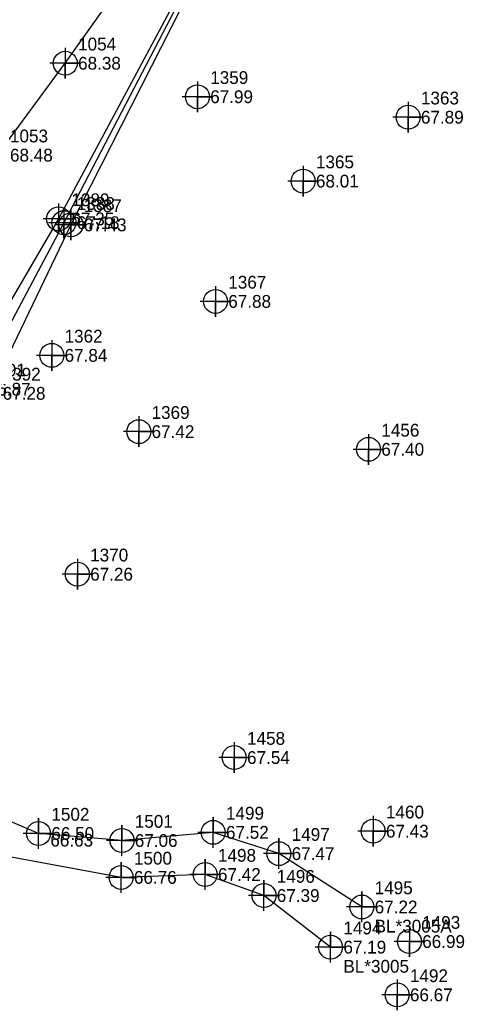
# Model space of a CAD drawing. Extents: x 2062781 to 2066835, y 358981 to 366501.
# Drawn here: x 2066461.7 to 2066548.6, y 365960.1 to 366153.9 of the extents above; entities that cross this region are included whole.
import ezdxf

# ---------------------------------------------------------------- set-up
doc = ezdxf.new("R2010")
doc.units = 0
for name, color, linetype in [('Exist DTM Breakline', 7, 'Continuous'), ('Exist DTM Breakline Cogo Elevation', 7, 'Continuous'), ('Exist DTM Breakline Cogo Number', 7, 'Continuous'), ('Exist DTM Breakline Cogo Point CELL', 7, 'Continuous'), ('Exist DTM Regular Point CELL', 7, 'Continuous'), ('Exist DTM Regular Point Cogo Elevation', 7, 'Continuous'), ('Exist DTM Regular Point Cogo Number', 7, 'Continuous'), ('Exist DTM Ridgeline', 7, 'Continuous'), ('Exist DTM Ridgeline Cogo Elevation', 7, 'Continuous'), ('Exist DTM Ridgeline Cogo Number', 7, 'Continuous'), ('Exist DTM Ridgeline Cogo Point CELL', 7, 'Continuous'), ('Exist Roads EOP', 7, 'Continuous'), ('Exist Roads EOP Cogo Elevation', 7, 'Continuous'), ('Exist Roads EOP Cogo Number', 7, 'Continuous'), ('Exist Roads EOP Cogo Point CELL', 7, 'Continuous'), ('Exist Roads Soil', 7, 'Continuous'), ('Exist Roads Soil Cogo Comment', 7, 'Continuous'), ('Exist Roads Soil Cogo Elevation', 7, 'Continuous'), ('Exist Roads Soil Cogo Number', 7, 'Continuous'), ('Exist Roads Soil Cogo Point CELL', 7, 'Continuous')]:
    doc.layers.add(name, color=color, linetype=linetype)

msp = doc.modelspace()

# ---------------------------------------------------------------- linework, layer by layer
at = {"layer": 'Exist DTM Breakline'}
msp.add_lwpolyline([(2066502.59, 366180.16), (2066494.49, 366160.63), (2066470.36, 366114.18), (2066452.98, 366081.59), (2066430.77, 366031.3)], dxfattribs=at)
at = {"layer": 'Exist DTM Breakline Cogo Point CELL'}
msp.add_lwpolyline([(2066470.36, 366117.18), (2066470.36, 366111.18), (2066470.36, 366114.18), (2066473.36, 366114.18), (2066467.36, 366114.18)], dxfattribs=at)
msp.add_circle((2066470.36, 366114.18), 2.34, dxfattribs=at)
at = {"layer": 'Exist DTM Regular Point CELL'}
for points in [[(2066496.44, 366141.83), (2066496.44, 366135.83), (2066496.44, 366138.83), (2066499.44, 366138.83), (2066493.44, 366138.83)], [(2066537.62, 366137.82), (2066537.62, 366131.82), (2066537.62, 366134.82), (2066540.62, 366134.82), (2066534.62, 366134.82)], [(2066517.1, 366125.32), (2066517.1, 366119.32), (2066517.1, 366122.32), (2066520.1, 366122.32), (2066514.1, 366122.32)], [(2066499.97, 366101.78), (2066499.97, 366095.78), (2066499.97, 366098.78), (2066502.97, 366098.78), (2066496.97, 366098.78)], [(2066467.98, 366091.22), (2066467.98, 366085.22), (2066467.98, 366088.22), (2066470.98, 366088.22), (2066464.98, 366088.22)], [(2066484.98, 366076.29), (2066484.98, 366070.29), (2066484.98, 366073.29), (2066487.98, 366073.29), (2066481.98, 366073.29)], [(2066529.88, 366072.83), (2066529.88, 366066.83), (2066529.88, 366069.83), (2066532.88, 366069.83), (2066526.88, 366069.83)], [(2066472.98, 366048.4), (2066472.98, 366042.4), (2066472.98, 366045.4), (2066475.98, 366045.4), (2066469.98, 366045.4)], [(2066503.64, 366012.52), (2066503.64, 366006.52), (2066503.64, 366009.52), (2066506.64, 366009.52), (2066500.64, 366009.52)], [(2066530.78, 365998.11), (2066530.78, 365992.11), (2066530.78, 365995.11), (2066533.78, 365995.11), (2066527.78, 365995.11)], [(2066537.87, 365976.51), (2066537.87, 365970.51), (2066537.87, 365973.51), (2066540.87, 365973.51), (2066534.87, 365973.51)], [(2066535.47, 365966.08), (2066535.47, 365960.08), (2066535.47, 365963.08), (2066538.47, 365963.08), (2066532.47, 365963.08)]]:
    msp.add_lwpolyline(points, dxfattribs=at)
for centre in [(2066496.44, 366138.83), (2066537.62, 366134.82), (2066517.1, 366122.32), (2066499.97, 366098.78), (2066467.98, 366088.22), (2066484.98, 366073.29), (2066529.88, 366069.83), (2066472.98, 366045.4), (2066503.64, 366009.52), (2066530.78, 365995.11), (2066537.87, 365973.51), (2066535.47, 365963.08)]:
    msp.add_circle(centre, 2.34, dxfattribs=at)
at = {"layer": 'Exist DTM Ridgeline'}
for points in [[(2066501.78, 366180.58), (2066493.93, 366161.06), (2066469.32, 366114.92), (2066450.36, 366082.49), (2066428.47, 366032.58)], [(2066503.5, 366179.71), (2066495.31, 366160.25), (2066471.73, 366113.76), (2066455.88, 366080.79), (2066433.24, 366030.24)]]:
    msp.add_lwpolyline(points, dxfattribs=at)
at = {"layer": 'Exist DTM Ridgeline Cogo Point CELL'}
for points in [[(2066469.32, 366117.92), (2066469.32, 366111.92), (2066469.32, 366114.92), (2066472.32, 366114.92), (2066466.32, 366114.92)], [(2066471.73, 366116.76), (2066471.73, 366110.76), (2066471.73, 366113.76), (2066474.73, 366113.76), (2066468.73, 366113.76)]]:
    msp.add_lwpolyline(points, dxfattribs=at)
for centre in [(2066469.32, 366114.92), (2066471.73, 366113.76)]:
    msp.add_circle(centre, 2.34, dxfattribs=at)
at = {"layer": 'Exist Roads EOP'}
msp.add_lwpolyline([(2066402.7, 366021.61), (2066413.52, 366042.85), (2066436.44, 366087.8), (2066457.31, 366127.4), (2066470.62, 366145.38), (2066484.82, 366165.44), (2066489.78, 366172.83), (2066491.22, 366174.84), (2066494.73, 366177.66), (2066498.24, 366180.15)], dxfattribs=at)
at = {"layer": 'Exist Roads EOP Cogo Point CELL'}
msp.add_lwpolyline([(2066470.62, 366148.38), (2066470.62, 366142.38), (2066470.62, 366145.38), (2066473.62, 366145.38), (2066467.62, 366145.38)], dxfattribs=at)
msp.add_circle((2066470.62, 366145.38), 2.34, dxfattribs=at)
at = {"layer": 'Exist Roads Soil'}
for points in [[(2066528.58, 365980.28), (2066512.36, 365990.72), (2066499.52, 365994.88), (2066481.7, 365993.28), (2066465.4, 365994.66), (2066450.12, 366001.21), (2066430.48, 366010.74), (2066407.05, 366015.41)], [(2066481.53, 365986.07), (2066446.25, 365992.58), (2066424.19, 366000.79), (2066400, 366001.24)], [(2066522.47, 365972.42), (2066509.45, 365982.52), (2066497.96, 365986.63), (2066481.53, 365986.07)]]:
    msp.add_lwpolyline(points, dxfattribs=at)
at = {"layer": 'Exist Roads Soil Cogo Point CELL'}
for points in [[(2066465.4, 365991.66), (2066465.4, 365997.66), (2066465.4, 365994.66), (2066468.4, 365994.66), (2066462.4, 365994.66)], [(2066481.7, 365990.28), (2066481.7, 365996.28), (2066481.7, 365993.28), (2066484.7, 365993.28), (2066478.7, 365993.28)], [(2066499.52, 365991.88), (2066499.52, 365997.88), (2066499.52, 365994.88), (2066502.52, 365994.88), (2066496.52, 365994.88)], [(2066512.36, 365987.72), (2066512.36, 365993.72), (2066512.36, 365990.72), (2066515.36, 365990.72), (2066509.36, 365990.72)], [(2066481.53, 365983.07), (2066481.53, 365989.07), (2066481.53, 365986.07), (2066484.53, 365986.07), (2066478.53, 365986.07)], [(2066497.96, 365983.63), (2066497.96, 365989.63), (2066497.96, 365986.63), (2066500.96, 365986.63), (2066494.96, 365986.63)], [(2066509.45, 365979.52), (2066509.45, 365985.52), (2066509.45, 365982.52), (2066512.45, 365982.52), (2066506.45, 365982.52)], [(2066528.58, 365977.28), (2066528.58, 365983.28), (2066528.58, 365980.28), (2066531.58, 365980.28), (2066525.58, 365980.28)], [(2066522.47, 365969.42), (2066522.47, 365975.42), (2066522.47, 365972.42), (2066525.47, 365972.42), (2066519.47, 365972.42)]]:
    msp.add_lwpolyline(points, dxfattribs=at)
for centre in [(2066465.4, 365994.66), (2066499.52, 365994.88), (2066481.7, 365993.28), (2066512.36, 365990.72), (2066481.53, 365986.07), (2066497.96, 365986.63), (2066509.45, 365982.52), (2066528.58, 365980.28), (2066522.47, 365972.42)]:
    msp.add_circle(centre, 2.34, dxfattribs=at)

# ---------------------------------------------------------------- texts
at = {"layer": 'Exist DTM Breakline Cogo Elevation'}
for s, p in [('67.18', (2066472.86, 366112.93)), ('66.87', (2066455.48, 366080.34))]:
    msp.add_text(s, height=2.5, dxfattribs=at).set_placement(p)
at = {"layer": 'Exist DTM Breakline Cogo Number'}
for s, p in [('1388', (2066472.86, 366116.68)), ('1391', (2066455.48, 366084.09))]:
    msp.add_text(s, height=2.5, dxfattribs=at).set_placement(p)
at = {"layer": 'Exist DTM Regular Point Cogo Elevation'}
for s, p in [('67.99', (2066498.94, 366137.58)), ('67.89', (2066540.12, 366133.57)), ('68.01', (2066519.6, 366121.07)), ('67.88', (2066502.47, 366097.53)), ('67.84', (2066470.48, 366086.97)), ('67.42', (2066487.48, 366072.04)), ('67.40', (2066532.38, 366068.58)), ('67.26', (2066475.48, 366044.15)), ('67.54', (2066506.14, 366008.27)), ('67.43', (2066533.28, 365993.86)), ('66.99', (2066540.37, 365972.26)), ('66.67', (2066537.97, 365961.83))]:
    msp.add_text(s, height=2.5, dxfattribs=at).set_placement(p)
at = {"layer": 'Exist DTM Regular Point Cogo Number'}
for s, p in [('1359', (2066498.94, 366141.33)), ('1363', (2066540.12, 366137.32)), ('1365', (2066519.6, 366124.82)), ('1367', (2066502.47, 366101.28)), ('1362', (2066470.48, 366090.72)), ('1369', (2066487.48, 366075.79)), ('1456', (2066532.38, 366072.33)), ('1370', (2066475.48, 366047.9)), ('1458', (2066506.14, 366012.02)), ('1460', (2066533.28, 365997.61)), ('1493', (2066540.37, 365976.01)), ('1492', (2066537.97, 365965.58))]:
    msp.add_text(s, height=2.5, dxfattribs=at).set_placement(p)
at = {"layer": 'Exist DTM Ridgeline Cogo Elevation'}
for s, p in [('67.35', (2066471.82, 366113.67)), ('67.43', (2066474.23, 366112.51)), ('67.28', (2066458.38, 366079.54))]:
    msp.add_text(s, height=2.5, dxfattribs=at).set_placement(p)
at = {"layer": 'Exist DTM Ridgeline Cogo Number'}
for s, p in [('1389', (2066471.82, 366117.42)), ('1387', (2066474.23, 366116.26)), ('1392', (2066458.38, 366083.29))]:
    msp.add_text(s, height=2.5, dxfattribs=at).set_placement(p)
at = {"layer": 'Exist Roads EOP Cogo Elevation'}
for s, p in [('68.38', (2066473.12, 366144.13)), ('68.48', (2066459.81, 366126.15))]:
    msp.add_text(s, height=2.5, dxfattribs=at).set_placement(p)
at = {"layer": 'Exist Roads EOP Cogo Number'}
for s, p in [('1054', (2066473.12, 366147.88)), ('1053', (2066459.81, 366129.9))]:
    msp.add_text(s, height=2.5, dxfattribs=at).set_placement(p)
at = {"layer": 'Exist Roads Soil Cogo Comment'}
for s, p in [('BL*3005A', (2066531.08, 365975.28)), ('BL*3005', (2066524.97, 365967.42))]:
    msp.add_text(s, height=2.5, dxfattribs=at).set_placement(p)
at = {"layer": 'Exist Roads Soil Cogo Elevation'}
for s, p in [('67.52', (2066502.02, 365993.63)), ('66.63', (2066467.69, 365992.11)), ('66.50', (2066467.9, 365993.41)), ('67.06', (2066484.2, 365992.03)), ('67.47', (2066514.86, 365989.47)), ('66.76', (2066484.03, 365984.82)), ('67.42', (2066500.46, 365985.38)), ('67.39', (2066511.95, 365981.27)), ('67.22', (2066531.08, 365979.03)), ('67.19', (2066524.97, 365971.17))]:
    msp.add_text(s, height=2.5, dxfattribs=at).set_placement(p)
at = {"layer": 'Exist Roads Soil Cogo Number'}
for s, p in [('1502', (2066467.9, 365997.16)), ('1501', (2066484.2, 365995.78)), ('1499', (2066502.02, 365997.38)), ('1497', (2066514.86, 365993.22)), ('1500', (2066484.03, 365988.57)), ('1498', (2066500.46, 365989.13)), ('1496', (2066511.95, 365985.02)), ('1495', (2066531.08, 365982.78)), ('1494', (2066524.97, 365974.92))]:
    msp.add_text(s, height=2.5, dxfattribs=at).set_placement(p)

doc.saveas('drawing.dxf')
